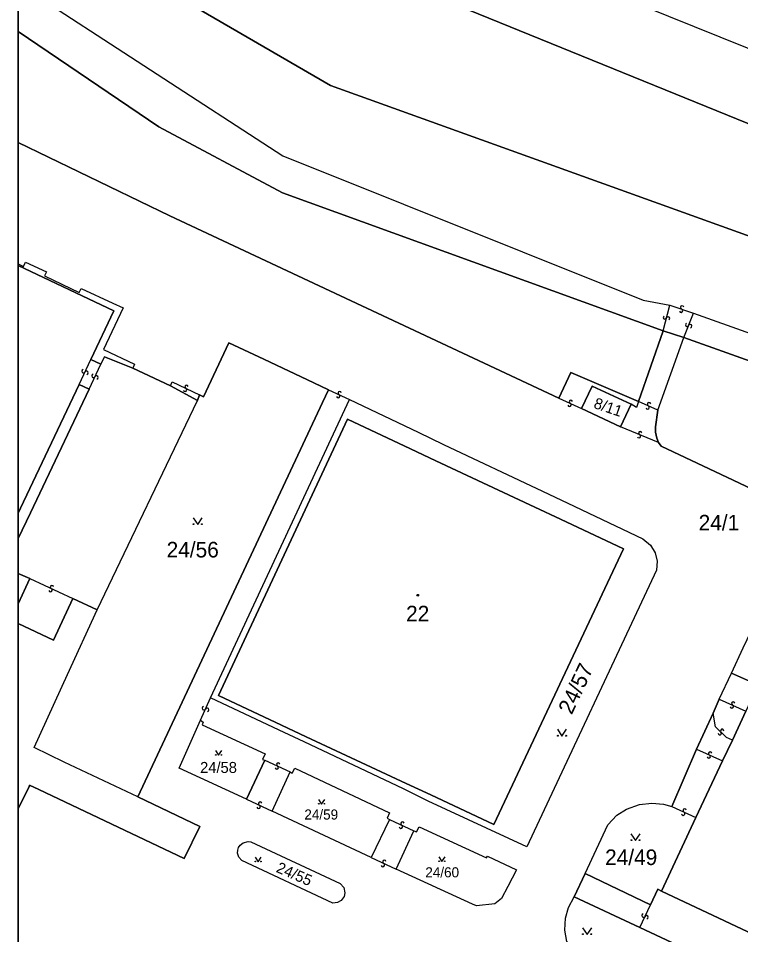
# Model space of a CAD drawing. Extents: x -600309 to -598967, y -1161267 to -1160292.
# Drawn here: x -600308.5 to -600229.8, y -1161142.4 to -1161042.5 of the extents above; entities that cross this region are included whole.
import ezdxf

# ---------------------------------------------------------------- set-up
doc = ezdxf.new("R2010")
doc.units = 0
for name, color, linetype in [('Level 1', 7, 'Continuous'), ('Level 13', 7, 'Continuous'), ('Level 3', 7, 'Continuous'), ('Level 4', 7, 'Continuous'), ('Level 5', 7, 'Continuous'), ('Level 57', 7, 'Continuous'), ('Level 60', 7, 'Continuous'), ('Vrstva 60', 7, 'Continuous'), ('Vrstva 63', 7, 'Continuous')]:
    doc.layers.add(name, color=color, linetype=linetype)

msp = doc.modelspace()

# ---------------------------------------------------------------- linework, layer by layer
at = {"layer": 'Level 1'}
for p, q in [((-600308.541, -1161103.014), (-600307.29, -1161103.59)), ((-600307.29, -1161103.59), (-600308.541, -1161106.322))]:
    msp.add_line(p, q, dxfattribs=at)
for points in [[(-600308.541, -1161016.585), (-600293.63, -1161026), (-600269.66, -1161037.42), (-600029.19, -1161135.15), (-600013.53, -1161140.37), (-599983.56, -1161149.75), (-599958.61, -1161155.76), (-599866.12, -1161178.6), (-599796.72, -1161205.03)], [(-600308.541, -1161029.185), (-600296.3, -1161037.15), (-600274.49, -1161049.84), (-600189.74, -1161080.33), (-600110.03, -1161111.48), (-600017.61, -1161148.92), (-599998.66, -1161155.17), (-599968.04, -1161161.44), (-599947.72, -1161166.65), (-599940.7, -1161168.31), (-599932.71, -1161170.39), (-599873.45, -1161186.23), (-599868.39, -1161187.94)], [(-600308.541, -1161043.954), (-600293.21, -1161054.34), (-600279.72, -1161061.52), (-600238.21, -1161076.58)], [(-600308.541, -1161056.042), (-600292.03, -1161064.03), (-600249.61, -1161083.91)], [(-600300.64, -1161079.71), (-600298.12, -1161074.39), (-600308.541, -1161069.469)], [(-600240.9, -1161084.3), (-600238.21, -1161076.58)], [(-600238.79, -1161085.21), (-600235.97, -1161077.32)], [(-600238.21, -1161076.58), (-600235.97, -1161077.32)], [(-599974.47, -1161183.5), (-599997.2, -1161172.33), (-600007.91, -1161167.09), (-600016.11, -1161163.4), (-600021.76, -1161161.11), (-600035.71, -1161155.39), (-600038.43, -1161154.23), (-600085.92, -1161135.07), (-600119.48, -1161121.36), (-600136.33, -1161114.57), (-600158.74, -1161105.59), (-600181.17, -1161096.78), (-600189.72, -1161093.73), (-600201.12, -1161089.75), (-600235.97, -1161077.32)], [(-600274.72, -1161083), (-600276.33, -1161082.24), (-600281.78, -1161079.66), (-600285.57, -1161077.87), (-600288.34, -1161083.77), (-600288.8, -1161083.55)], [(-600299.55, -1161080.23), (-600300.64, -1161079.71)], [(-600296.07, -1161080.64), (-600299.16, -1161079.4), (-600299.55, -1161080.23)], [(-600291.94, -1161082.58), (-600296.07, -1161080.64)], [(-600240.9, -1161084.3), (-600248.3, -1161081.11), (-600249.61, -1161083.91)], [(-600308.541, -1161096.451), (-600308.29, -1161095.92), (-600301.92, -1161082.43)], [(-600300.83, -1161082.94), (-600307.23, -1161096.43), (-600308.541, -1161099.202)], [(-600301.92, -1161082.43), (-600300.83, -1161082.94)], [(-600295.52, -1161127.38), (-600275.37, -1161084.4), (-600274.72, -1161083)], [(-600289.01, -1161084.16), (-600291.94, -1161082.58)], [(-600241.72, -1161084.59), (-600245.98, -1161082.6), (-600247.12, -1161085.04)], [(-600299.94, -1161107), (-600289.01, -1161084.16)], [(-600288.8, -1161083.55), (-600289.01, -1161084.16)], [(-600287.58, -1161116.57), (-600272.44, -1161084.07)], [(-600272.44, -1161084.07), (-600264.93, -1161087.64), (-600262.18, -1161088.98), (-600251.4, -1161094.05), (-600248.61, -1161095.37), (-600240.46, -1161099.25), (-600239.6, -1161099.93), (-600239.08, -1161100.76), (-600238.88, -1161101.7), (-600238.97, -1161102.67), (-600253.1, -1161132.84), (-600263.85, -1161127.84), (-600266.54, -1161126.49), (-600277.38, -1161121.38), (-600280.08, -1161120.1), (-600287.58, -1161116.57)], [(-600247.12, -1161085.04), (-600242.86, -1161087.03)], [(-600242.86, -1161087.03), (-600241.72, -1161084.59)], [(-600238.79, -1161085.21), (-600239.05, -1161087.03), (-600239.07, -1161087.61), (-600238.93, -1161088.28), (-600238.73, -1161088.76)], [(-600286.73, -1161116.34), (-600272.63, -1161086.22), (-600265.77, -1161089.44), (-600263, -1161090.74), (-600252.22, -1161095.8), (-600249.43, -1161097.11), (-600242.56, -1161100.34), (-600256.68, -1161130.39), (-600263.56, -1161127.17), (-600266.26, -1161125.91), (-600277.14, -1161120.82), (-600279.84, -1161119.56), (-600286.73, -1161116.34)], [(-600238.73, -1161088.76), (-600238.46, -1161089.16), (-600151.25, -1161130.33), (-600098.6, -1161155.15)], [(-600308.541, -1161108.492), (-600304.69, -1161110.29), (-600302.61, -1161105.76)], [(-600302.61, -1161105.76), (-600299.94, -1161107)], [(-600295.52, -1161127.38), (-600303.53, -1161123.58), (-600306.83, -1161122.01), (-600303.17, -1161114.03), (-600299.94, -1161107)], [(-600230.78, -1161113.91), (-600229.5, -1161111.12)], [(-600232.11, -1161116.71), (-600230.78, -1161113.91)], [(-600228.8, -1161114.76), (-600230.78, -1161113.91)], [(-600232.11, -1161116.71), (-600232.78, -1161118.25)], [(-600232.78, -1161118.25), (-600234.6, -1161122.19)], [(-600229.2, -1161118.03), (-600230.66, -1161121.19)], [(-600283.65, -1161127.64), (-600291.02, -1161124.24), (-600288.68, -1161119.03)], [(-600288.68, -1161119.03), (-600288.4, -1161119.22), (-600288.5, -1161119.52), (-600281.62, -1161122.69), (-600281.93, -1161123.29), (-600281.65, -1161123.36)], [(-600231.76, -1161123.46), (-600230.66, -1161121.19)], [(-600234.6, -1161122.19), (-600237.27, -1161128.43)], [(-600283.65, -1161127.64), (-600281.65, -1161123.36)], [(-600278.91, -1161124.66), (-600278.68, -1161124.81), (-600278.4, -1161124.25), (-600268.07, -1161129.13), (-600268.33, -1161129.69), (-600268.07, -1161129.83)], [(-600234.65, -1161129.64), (-600231.76, -1161123.46)], [(-600280.87, -1161128.92), (-600278.91, -1161124.66)], [(-600308.541, -1161128.696), (-600307.37, -1161126.23), (-600307.31, -1161126.09), (-600306.29, -1161126.59), (-600290.44, -1161134.11), (-600288.76, -1161130.59), (-600295.52, -1161127.38)], [(-600246.72, -1161135.74), (-600244.26, -1161130.43), (-600243.29, -1161129.37), (-600242.24, -1161128.72), (-600240.8, -1161128.21), (-600239.45, -1161128.05), (-600238.2, -1161128.16), (-600237.27, -1161128.43)], [(-600270.08, -1161134), (-600280.87, -1161128.92)], [(-600268.07, -1161129.83), (-600270.08, -1161134)], [(-600238.39, -1161137.67), (-600234.65, -1161129.64)], [(-600265.4, -1161131.08), (-600265.14, -1161131.2), (-600264.82, -1161130.66), (-600257.49, -1161134.01), (-600257.37, -1161133.84), (-600254.23, -1161135.33), (-600255.15, -1161137.16), (-600255.84, -1161138.46), (-600256.59, -1161139.03), (-600258.57, -1161139.24), (-600259.01, -1161139.08), (-600267.34, -1161135.27)], [(-600267.34, -1161135.27), (-600265.4, -1161131.08)], [(-600283.2, -1161132.29), (-600273.43, -1161136.82), (-600273.06, -1161137.26), (-600272.93, -1161137.82), (-600273.02, -1161138.23), (-600273.34, -1161138.67), (-600273.73, -1161138.89), (-600274.25, -1161138.95), (-600284.17, -1161134.33), (-600284.51, -1161133.96), (-600284.63, -1161133.51), (-600284.62, -1161133.19), (-600284.52, -1161132.89), (-600284.34, -1161132.63), (-600284.01, -1161132.37), (-600283.48, -1161132.25), (-600283.2, -1161132.29)], [(-600246.72, -1161135.74), (-600247.94, -1161138.28)], [(-600246.72, -1161135.74), (-600239.62, -1161139.16)], [(-600239.62, -1161139.16), (-600238.82, -1161137.44), (-600238.39, -1161137.67)], [(-600238.39, -1161137.67), (-600224.67, -1161144.13), (-600224.93, -1161144.74), (-600183.7, -1161164.11), (-600183.4, -1161163.46), (-600169.68, -1161169.91), (-600159.11, -1161147.29)], [(-600238.42, -1161148.87), (-600246.26, -1161145.13), (-600247.67, -1161144.2), (-600248.73, -1161143.15), (-600248.94, -1161141.91), (-600248.86, -1161140.6), (-600248.54, -1161139.42), (-600247.94, -1161138.28)], [(-600240.77, -1161141.63), (-600247.94, -1161138.28)], [(-600240.77, -1161141.63), (-600236.13, -1161143.78), (-600238.42, -1161148.87)]]:
    msp.add_lwpolyline(points, dxfattribs=at)
at = {"layer": 'Level 13'}
for centre, start, end in [((-600236.281, -1161074.384), 198.05713, 70.64713), ((-600236.158, -1161074.036), 18.27158, 250.36958), ((-600238.038, -1161075.133), 113.19265, 345.29065), ((-600237.682, -1161075.226), 292.9782, 165.5682), ((-600235.621, -1161075.921), 106.01836, 338.11635), ((-600235.279, -1161076.058), 285.8039, 158.3939), ((-600301.446, -1161080.99), 102.17161, 334.26961), ((-600301.114, -1161081.149), 281.95715, 154.54715), ((-600300.356, -1161081.5), 102.09021, 334.18821), ((-600300.024, -1161081.659), 281.87575, 154.46575), ((-600290.36, -1161083.016), 191.61206, 64.20206), ((-600290.199, -1161082.684), 11.82651, 243.92451), ((-600273.5, -1161083.374), 12.23215, 244.33015), ((-600273.659, -1161083.706), 192.01769, 64.60769), ((-600248.282, -1161084.313), 12.96346, 245.06146), ((-600248.437, -1161084.647), 192.74901, 65.33901), ((-600239.915, -1161084.919), 194.04318, 66.14118), ((-600239.766, -1161084.581), 13.82873, 246.41873), ((-600240.863, -1161088.069), 194.6446, 66.74259), ((-600240.718, -1161087.731), 14.43014, 247.02014), ((-600305.028, -1161104.847), 192.28229, 64.87229), ((-600304.871, -1161104.513), 12.49675, 244.59474), ((-600230.582, -1161117.203), 12.9733, 245.07129), ((-600288.298, -1161117.723), 103.28071, 335.37871), ((-600287.962, -1161117.876), 283.06626, 155.65626), ((-600230.737, -1161117.537), 192.75884, 65.34884), ((-600231.791, -1161120.188), 353.1293, 225.7193), ((-600232.049, -1161120.451), 173.34376, 45.44175), ((-600233.256, -1161122.988), 193.06489, 65.65489), ((-600233.103, -1161122.652), 13.27935, 245.37734), ((-600280.36, -1161124.176), 191.77616, 64.36616), ((-600280.199, -1161123.844), 11.99061, 244.08861), ((-600282.181, -1161128.113), 12.64989, 244.74789), ((-600282.338, -1161128.447), 192.43544, 65.02544), ((-600236.038, -1161129.207), 192.36927, 64.95927), ((-600235.881, -1161128.873), 12.58373, 244.68173), ((-600266.66, -1161130.294), 12.28539, 244.38339), ((-600266.819, -1161130.626), 192.07094, 64.66094), ((-600268.788, -1161134.807), 192.29038, 64.88038), ((-600268.631, -1161134.473), 12.50484, 244.60284), ((-600240.366, -1161140.321), 102.40666, 334.50465), ((-600240.033, -1161140.478), 282.1922, 154.7822)]:
    msp.add_arc(centre, 0.184, start, end, dxfattribs=at)
at = {"layer": 'Level 3'}
for points in [[(-600066.21, -1161108.54), (-600067.74, -1161109.99), (-600069.58, -1161110.09), (-600115.09, -1161091.62), (-600246.17, -1161038.84), (-600272.96, -1161027.28), (-600294.57, -1161016.1), (-600302.87, -1161010.53), (-600308.541, -1161006.93)], [(-600308.541, -1161038.707), (-600279.69, -1161057.5), (-600240.4, -1161073.22), (-600237.5, -1161073.77)], [(-600308.541, -1161069.283), (-600307.96, -1161069.56), (-600307.74, -1161069.09), (-600305.47, -1161070.14), (-600305.68, -1161070.6), (-600301.9, -1161072.39), (-600301.69, -1161071.95), (-600298.25, -1161073.58), (-600297.11, -1161074.08), (-600299.26, -1161078.62), (-600295.89, -1161080.23), (-600296.07, -1161080.64)], [(-600238.21, -1161076.58), (-600237.5, -1161073.77)], [(-600237.5, -1161073.77), (-600234.93, -1161074.66)], [(-600235.97, -1161077.32), (-600234.93, -1161074.66)], [(-600234.93, -1161074.66), (-600208.54, -1161084.06), (-600208.48, -1161084.37), (-600195.12, -1161088.82), (-600111.77, -1161121.94), (-600010.7, -1161163.25), (-599975.33, -1161178.89), (-599974.93, -1161179.15), (-599974.69, -1161181.32), (-599973.94, -1161183.71)], [(-600301.92, -1161082.43), (-600300.64, -1161079.71)], [(-600300.83, -1161082.94), (-600299.55, -1161080.23)], [(-600291.94, -1161082.58), (-600291.75, -1161082.14), (-600288.8, -1161083.55)], [(-600274.72, -1161083), (-600272.44, -1161084.07)], [(-600249.61, -1161083.91), (-600247.12, -1161085.04)], [(-600240.9, -1161084.3), (-600241.13, -1161084.93), (-600241.72, -1161084.59)], [(-600238.79, -1161085.21), (-600240.9, -1161084.3)], [(-600238.73, -1161088.76), (-600242.86, -1161087.03)], [(-600307.29, -1161103.59), (-600302.61, -1161105.76)], [(-600288.68, -1161119.03), (-600287.58, -1161116.57)], [(-600232.11, -1161116.71), (-600229.2, -1161118.03)], [(-600230.66, -1161121.19), (-600231.32, -1161120.9), (-600232.52, -1161119.74), (-600232.78, -1161118.25)], [(-600234.6, -1161122.19), (-600231.76, -1161123.46)], [(-600281.65, -1161123.36), (-600278.91, -1161124.66)], [(-600283.65, -1161127.64), (-600280.87, -1161128.92)], [(-600237.27, -1161128.43), (-600234.65, -1161129.64)], [(-600268.07, -1161129.83), (-600265.4, -1161131.08)], [(-600270.08, -1161134), (-600267.34, -1161135.27)], [(-600240.77, -1161141.63), (-600239.62, -1161139.16)]]:
    msp.add_lwpolyline(points, dxfattribs=at)
at = {"layer": 'Level 5'}
for points in [[(-600289.481, -1161096.95), (-600288.98, -1161097.7), (-600288.48, -1161096.95)], [(-600249.761, -1161120.01), (-600249.26, -1161120.76), (-600248.76, -1161120.01)], [(-600287.041, -1161122.33), (-600286.7, -1161122.84), (-600286.36, -1161122.33)], [(-600275.811, -1161127.65), (-600275.47, -1161128.16), (-600275.13, -1161127.65)], [(-600241.741, -1161131.4), (-600241.24, -1161132.15), (-600240.74, -1161131.4)], [(-600282.731, -1161133.94), (-600282.39, -1161134.45), (-600282.05, -1161133.94)], [(-600262.691, -1161133.92), (-600262.35, -1161134.43), (-600262.01, -1161133.92)], [(-600247.021, -1161141.64), (-600246.52, -1161142.39), (-600246.02, -1161141.64)]]:
    msp.add_lwpolyline(points, dxfattribs=at)
for centre, radius in [((-600289.43, -1161097.65), 0.05), ((-600288.531, -1161097.65), 0.05), ((-600264.98, -1161105.4), 0.09), ((-600264.98, -1161105.4), 0.0521), ((-600249.71, -1161120.71), 0.05), ((-600248.811, -1161120.71), 0.05), ((-600287.006, -1161122.806), 0.034), ((-600286.395, -1161122.806), 0.034), ((-600275.776, -1161128.126), 0.034), ((-600275.165, -1161128.126), 0.034), ((-600241.69, -1161132.1), 0.05), ((-600240.791, -1161132.1), 0.05), ((-600282.696, -1161134.416), 0.034), ((-600282.085, -1161134.416), 0.034), ((-600262.656, -1161134.396), 0.034), ((-600262.045, -1161134.396), 0.034), ((-600246.97, -1161142.34), 0.05), ((-600246.071, -1161142.34), 0.05)]:
    msp.add_circle(centre, radius, dxfattribs=at)
at = {"layer": 'Level 60'}
for points in [[(-600098.6, -1161155.15), (-600151.25, -1161130.33), (-600238.46, -1161089.16), (-600238.73, -1161088.76), (-600238.93, -1161088.28), (-600239.07, -1161087.61), (-600239.05, -1161087.03), (-600238.79, -1161085.21), (-600235.97, -1161077.32), (-600201.12, -1161089.75), (-600189.72, -1161093.73), (-600181.17, -1161096.78), (-600158.74, -1161105.59), (-600136.33, -1161114.57), (-600119.48, -1161121.36), (-600085.92, -1161135.07)], [(-600228.8, -1161114.76), (-600230.78, -1161113.91), (-600229.5, -1161111.12)], [(-600224.67, -1161144.13), (-600238.39, -1161137.67), (-600234.65, -1161129.64), (-600231.76, -1161123.46), (-600230.66, -1161121.19), (-600229.2, -1161118.03)], [(-600236.13, -1161143.78), (-600240.77, -1161141.63), (-600247.94, -1161138.28), (-600246.72, -1161135.74), (-600239.62, -1161139.16), (-600238.82, -1161137.44), (-600238.39, -1161137.67), (-600224.67, -1161144.13)]]:
    msp.add_lwpolyline(points, dxfattribs=at)
for points in [[(-600299.94, -1161107), (-600289.01, -1161084.16), (-600288.8, -1161083.55), (-600288.34, -1161083.77), (-600285.57, -1161077.87), (-600281.78, -1161079.66), (-600276.33, -1161082.24), (-600274.72, -1161083), (-600275.37, -1161084.4), (-600295.52, -1161127.38), (-600303.53, -1161123.58), (-600306.83, -1161122.01), (-600303.17, -1161114.03)], [(-600245.98, -1161082.6), (-600241.72, -1161084.59), (-600242.86, -1161087.03), (-600247.12, -1161085.04)], [(-600287.58, -1161116.57), (-600272.44, -1161084.07), (-600264.93, -1161087.64), (-600262.18, -1161088.98), (-600251.4, -1161094.05), (-600248.61, -1161095.37), (-600240.46, -1161099.25), (-600239.6, -1161099.93), (-600239.08, -1161100.76), (-600238.88, -1161101.7), (-600238.97, -1161102.67), (-600253.1, -1161132.84), (-600263.85, -1161127.84), (-600266.54, -1161126.49), (-600277.38, -1161121.38), (-600280.08, -1161120.1)], [(-600272.63, -1161086.22), (-600286.73, -1161116.34), (-600279.84, -1161119.56), (-600277.14, -1161120.82), (-600266.26, -1161125.91), (-600263.56, -1161127.17), (-600256.68, -1161130.39), (-600242.56, -1161100.34), (-600249.43, -1161097.11), (-600252.22, -1161095.8), (-600263, -1161090.74), (-600265.77, -1161089.44)], [(-600286.73, -1161116.34), (-600272.63, -1161086.22), (-600265.77, -1161089.44), (-600263, -1161090.74), (-600252.22, -1161095.8), (-600249.43, -1161097.11), (-600242.56, -1161100.34), (-600256.68, -1161130.39), (-600263.56, -1161127.17), (-600266.26, -1161125.91), (-600277.14, -1161120.82), (-600279.84, -1161119.56)], [(-600232.78, -1161118.25), (-600232.11, -1161116.71), (-600230.78, -1161113.91), (-600228.8, -1161114.76), (-600227.86, -1161115.16), (-600229.2, -1161118.03), (-600230.66, -1161121.19), (-600231.76, -1161123.46), (-600234.65, -1161129.64), (-600238.39, -1161137.67), (-600238.82, -1161137.44), (-600239.62, -1161139.16), (-600246.72, -1161135.74), (-600244.26, -1161130.43), (-600243.29, -1161129.37), (-600242.24, -1161128.72), (-600240.8, -1161128.21), (-600239.45, -1161128.05), (-600238.2, -1161128.16), (-600237.27, -1161128.43), (-600234.6, -1161122.19)], [(-600283.65, -1161127.64), (-600291.02, -1161124.24), (-600288.68, -1161119.03), (-600288.4, -1161119.22), (-600288.5, -1161119.52), (-600281.62, -1161122.69), (-600281.93, -1161123.29), (-600281.65, -1161123.36)], [(-600280.87, -1161128.92), (-600278.91, -1161124.66), (-600278.68, -1161124.81), (-600278.4, -1161124.25), (-600268.07, -1161129.13), (-600268.33, -1161129.69), (-600268.07, -1161129.83), (-600270.08, -1161134)], [(-600267.34, -1161135.27), (-600265.4, -1161131.08), (-600265.14, -1161131.2), (-600264.82, -1161130.66), (-600257.49, -1161134.01), (-600257.37, -1161133.84), (-600254.23, -1161135.33), (-600255.15, -1161137.16), (-600255.84, -1161138.46), (-600256.59, -1161139.03), (-600258.57, -1161139.24), (-600259.01, -1161139.08)], [(-600283.2, -1161132.29), (-600273.43, -1161136.82), (-600273.06, -1161137.26), (-600272.93, -1161137.82), (-600273.02, -1161138.23), (-600273.34, -1161138.67), (-600273.73, -1161138.89), (-600274.25, -1161138.95), (-600284.17, -1161134.33), (-600284.51, -1161133.96), (-600284.63, -1161133.51), (-600284.62, -1161133.19), (-600284.52, -1161132.89), (-600284.34, -1161132.63), (-600284.01, -1161132.37), (-600283.48, -1161132.25)], [(-600238.42, -1161148.87), (-600246.26, -1161145.13), (-600247.67, -1161144.2), (-600248.73, -1161143.15), (-600248.94, -1161141.91), (-600248.86, -1161140.6), (-600248.54, -1161139.42), (-600247.94, -1161138.28), (-600240.77, -1161141.63), (-600236.13, -1161143.78)]]:
    msp.add_lwpolyline(points, close=True, dxfattribs=at)
at = {"layer": 'Vrstva 60'}
for points in [[(-600229.4, -1161041.08), (-600240.64, -1161036.86), (-600265.97, -1161026.56), (-600274.02, -1161023.09), (-600274.13, -1161023.31), (-600281.95, -1161019.95), (-600281.71, -1161019.75), (-600289.14, -1161016.48), (-600304.03, -1161006.33), (-600308.541, -1161003.513), (-600308.541, -1161016.585), (-600293.63, -1161026), (-600269.66, -1161037.42), (-600029.19, -1161135.15)], [(-600029.19, -1161135.15), (-600269.66, -1161037.42), (-600293.63, -1161026), (-600308.541, -1161016.585), (-600308.541, -1161029.185), (-600296.3, -1161037.15), (-600274.49, -1161049.84), (-600189.74, -1161080.33), (-600110.03, -1161111.48)], [(-600110.03, -1161111.48), (-600189.74, -1161080.33), (-600274.49, -1161049.84), (-600296.3, -1161037.15), (-600308.541, -1161029.185), (-600308.541, -1161043.954), (-600293.21, -1161054.34), (-600279.72, -1161061.52), (-600238.21, -1161076.58), (-600235.97, -1161077.32), (-600201.12, -1161089.75), (-600189.72, -1161093.73), (-600181.17, -1161096.78), (-600158.74, -1161105.59), (-600136.33, -1161114.57), (-600119.48, -1161121.36), (-600085.92, -1161135.07)], [(-600151.25, -1161130.33), (-600238.46, -1161089.16), (-600238.73, -1161088.76), (-600238.93, -1161088.28), (-600239.07, -1161087.61), (-600239.05, -1161087.03), (-600238.79, -1161085.21), (-600235.97, -1161077.32), (-600238.21, -1161076.58), (-600240.9, -1161084.3), (-600248.3, -1161081.11), (-600249.61, -1161083.91), (-600292.03, -1161064.03), (-600308.541, -1161056.042), (-600308.541, -1161069.469), (-600298.12, -1161074.39), (-600300.64, -1161079.71), (-600299.55, -1161080.23), (-600299.16, -1161079.4), (-600296.07, -1161080.64), (-600291.94, -1161082.58), (-600289.01, -1161084.16), (-600288.8, -1161083.55), (-600288.34, -1161083.77), (-600285.57, -1161077.87), (-600281.78, -1161079.66), (-600276.33, -1161082.24), (-600274.72, -1161083), (-600275.37, -1161084.4), (-600295.52, -1161127.38), (-600288.76, -1161130.59), (-600290.44, -1161134.11), (-600306.29, -1161126.59), (-600307.31, -1161126.09), (-600307.37, -1161126.23), (-600308.541, -1161128.696), (-600308.541, -1161158.838)], [(-600248.73, -1161143.15), (-600248.94, -1161141.91), (-600248.86, -1161140.6), (-600248.54, -1161139.42), (-600247.94, -1161138.28), (-600246.72, -1161135.74), (-600244.26, -1161130.43), (-600243.29, -1161129.37), (-600242.24, -1161128.72), (-600240.8, -1161128.21), (-600239.45, -1161128.05), (-600238.2, -1161128.16), (-600237.27, -1161128.43), (-600234.6, -1161122.19), (-600232.78, -1161118.25), (-600232.11, -1161116.71), (-600230.78, -1161113.91), (-600229.5, -1161111.12), (-600228.24, -1161108.47), (-600227.38, -1161107.25), (-600226.27, -1161106.69), (-600224.53, -1161106.8), (-600223.79, -1161107.23), (-600043.89, -1161191.9)]]:
    msp.add_lwpolyline(points, dxfattribs=at)
for points in [[(-600308.541, -1161043.954), (-600308.541, -1161056.042), (-600292.03, -1161064.03), (-600249.61, -1161083.91), (-600248.3, -1161081.11), (-600240.9, -1161084.3), (-600238.21, -1161076.58), (-600279.72, -1161061.52), (-600293.21, -1161054.34)], [(-600308.541, -1161069.469), (-600308.541, -1161096.451), (-600308.29, -1161095.92), (-600301.92, -1161082.43), (-600300.83, -1161082.94), (-600307.23, -1161096.43), (-600308.541, -1161099.202), (-600308.541, -1161103.014), (-600307.29, -1161103.59), (-600308.541, -1161106.322), (-600308.541, -1161108.492), (-600304.69, -1161110.29), (-600302.61, -1161105.76), (-600299.94, -1161107), (-600289.01, -1161084.16), (-600291.94, -1161082.58), (-600296.07, -1161080.64), (-600299.16, -1161079.4), (-600299.55, -1161080.23), (-600300.64, -1161079.71), (-600298.12, -1161074.39)], [(-600308.541, -1161096.451), (-600308.541, -1161099.202), (-600307.23, -1161096.43), (-600300.83, -1161082.94), (-600301.92, -1161082.43), (-600308.29, -1161095.92)], [(-600242.86, -1161087.03), (-600247.12, -1161085.04), (-600245.98, -1161082.6), (-600241.72, -1161084.59)], [(-600264.93, -1161087.64), (-600262.18, -1161088.98), (-600251.4, -1161094.05), (-600248.61, -1161095.37), (-600240.46, -1161099.25), (-600239.6, -1161099.93), (-600239.08, -1161100.76), (-600238.88, -1161101.7), (-600238.97, -1161102.67), (-600253.1, -1161132.84), (-600263.85, -1161127.84), (-600266.54, -1161126.49), (-600277.38, -1161121.38), (-600280.08, -1161120.1), (-600287.58, -1161116.57), (-600272.44, -1161084.07)], [(-600308.541, -1161106.322), (-600307.29, -1161103.59), (-600308.541, -1161103.014)], [(-600308.541, -1161128.696), (-600307.37, -1161126.23), (-600307.31, -1161126.09), (-600306.29, -1161126.59), (-600290.44, -1161134.11), (-600288.76, -1161130.59), (-600295.52, -1161127.38), (-600303.53, -1161123.58), (-600306.83, -1161122.01), (-600303.17, -1161114.03), (-600299.94, -1161107), (-600302.61, -1161105.76), (-600304.69, -1161110.29), (-600308.541, -1161108.492)], [(-600288.68, -1161119.03), (-600288.4, -1161119.22), (-600288.5, -1161119.52), (-600281.62, -1161122.69), (-600281.93, -1161123.29), (-600281.65, -1161123.36), (-600283.65, -1161127.64), (-600291.02, -1161124.24)], [(-600278.68, -1161124.81), (-600278.4, -1161124.25), (-600268.07, -1161129.13), (-600268.33, -1161129.69), (-600268.07, -1161129.83), (-600270.08, -1161134), (-600280.87, -1161128.92), (-600278.91, -1161124.66)], [(-600265.14, -1161131.2), (-600264.82, -1161130.66), (-600257.49, -1161134.01), (-600257.37, -1161133.84), (-600254.23, -1161135.33), (-600255.15, -1161137.16), (-600255.84, -1161138.46), (-600256.59, -1161139.03), (-600258.57, -1161139.24), (-600259.01, -1161139.08), (-600267.34, -1161135.27), (-600265.4, -1161131.08)], [(-600273.06, -1161137.26), (-600272.93, -1161137.82), (-600273.02, -1161138.23), (-600273.34, -1161138.67), (-600273.73, -1161138.89), (-600274.25, -1161138.95), (-600284.17, -1161134.33), (-600284.51, -1161133.96), (-600284.63, -1161133.51), (-600284.62, -1161133.19), (-600284.52, -1161132.89), (-600284.34, -1161132.63), (-600284.01, -1161132.37), (-600283.48, -1161132.25), (-600283.2, -1161132.29), (-600273.43, -1161136.82)]]:
    msp.add_lwpolyline(points, close=True, dxfattribs=at)
at = {"layer": 'Vrstva 63'}
msp.add_lwpolyline([(-600308.541, -1160292.347), (-598967.108, -1160292.347), (-598967.108, -1161267.031), (-600308.541, -1161267.031)], close=True, dxfattribs=at)

# ---------------------------------------------------------------- texts
at = {"layer": 'Level 4'}
for s, height, rotation, p in [('8/11', 1.2, 341.1, (-600245.89, -1161084.96)), ('24/57', 1.7, 64.8, (-600248.2, -1161118.5)), ('24/55', 1.2, 336.6, (-600280.52, -1161135.53))]:
    msp.add_text(s, height=height, rotation=rotation, dxfattribs=at).set_placement(p)
for s, height, p in [('24/56', 1.7, (-600292.37, -1161101.28)), ('22', 1.7, (-600266.26, -1161108.25)), ('24/58', 1.2, (-600288.72, -1161124.77)), ('24/59', 1.1, (-600277.35, -1161129.85)), ('24/49', 1.7, (-600244.56, -1161134.81)), ('24/60', 1.1, (-600264.16, -1161136.15))]:
    msp.add_text(s, height=height, dxfattribs=at).set_placement(p)
at = {"layer": 'Level 57'}
msp.add_text('24/1', height=1.7, dxfattribs=at).set_placement((-600234.36, -1161098.34))

doc.saveas('drawing.dxf')
